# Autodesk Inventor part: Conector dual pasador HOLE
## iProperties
Created: 2008-01
Part Number: Conector dual pasador HOLE
Document SubType Name: Modeling
Designer: eruiz-tagle
Mass: 0.299814 g
Surface Area: 8.49376 cm^2
Volume: 0.299814 cm^3
Density: 1 g/cm^3
Author: eruiz-tagle
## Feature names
1. Extrusion1
2. Hole1
3. Hole2
4. Mirror1
5. Extrusion2
6. Fillet1
7. Mirror2
8. Extrusion3
9. Extrusion4
